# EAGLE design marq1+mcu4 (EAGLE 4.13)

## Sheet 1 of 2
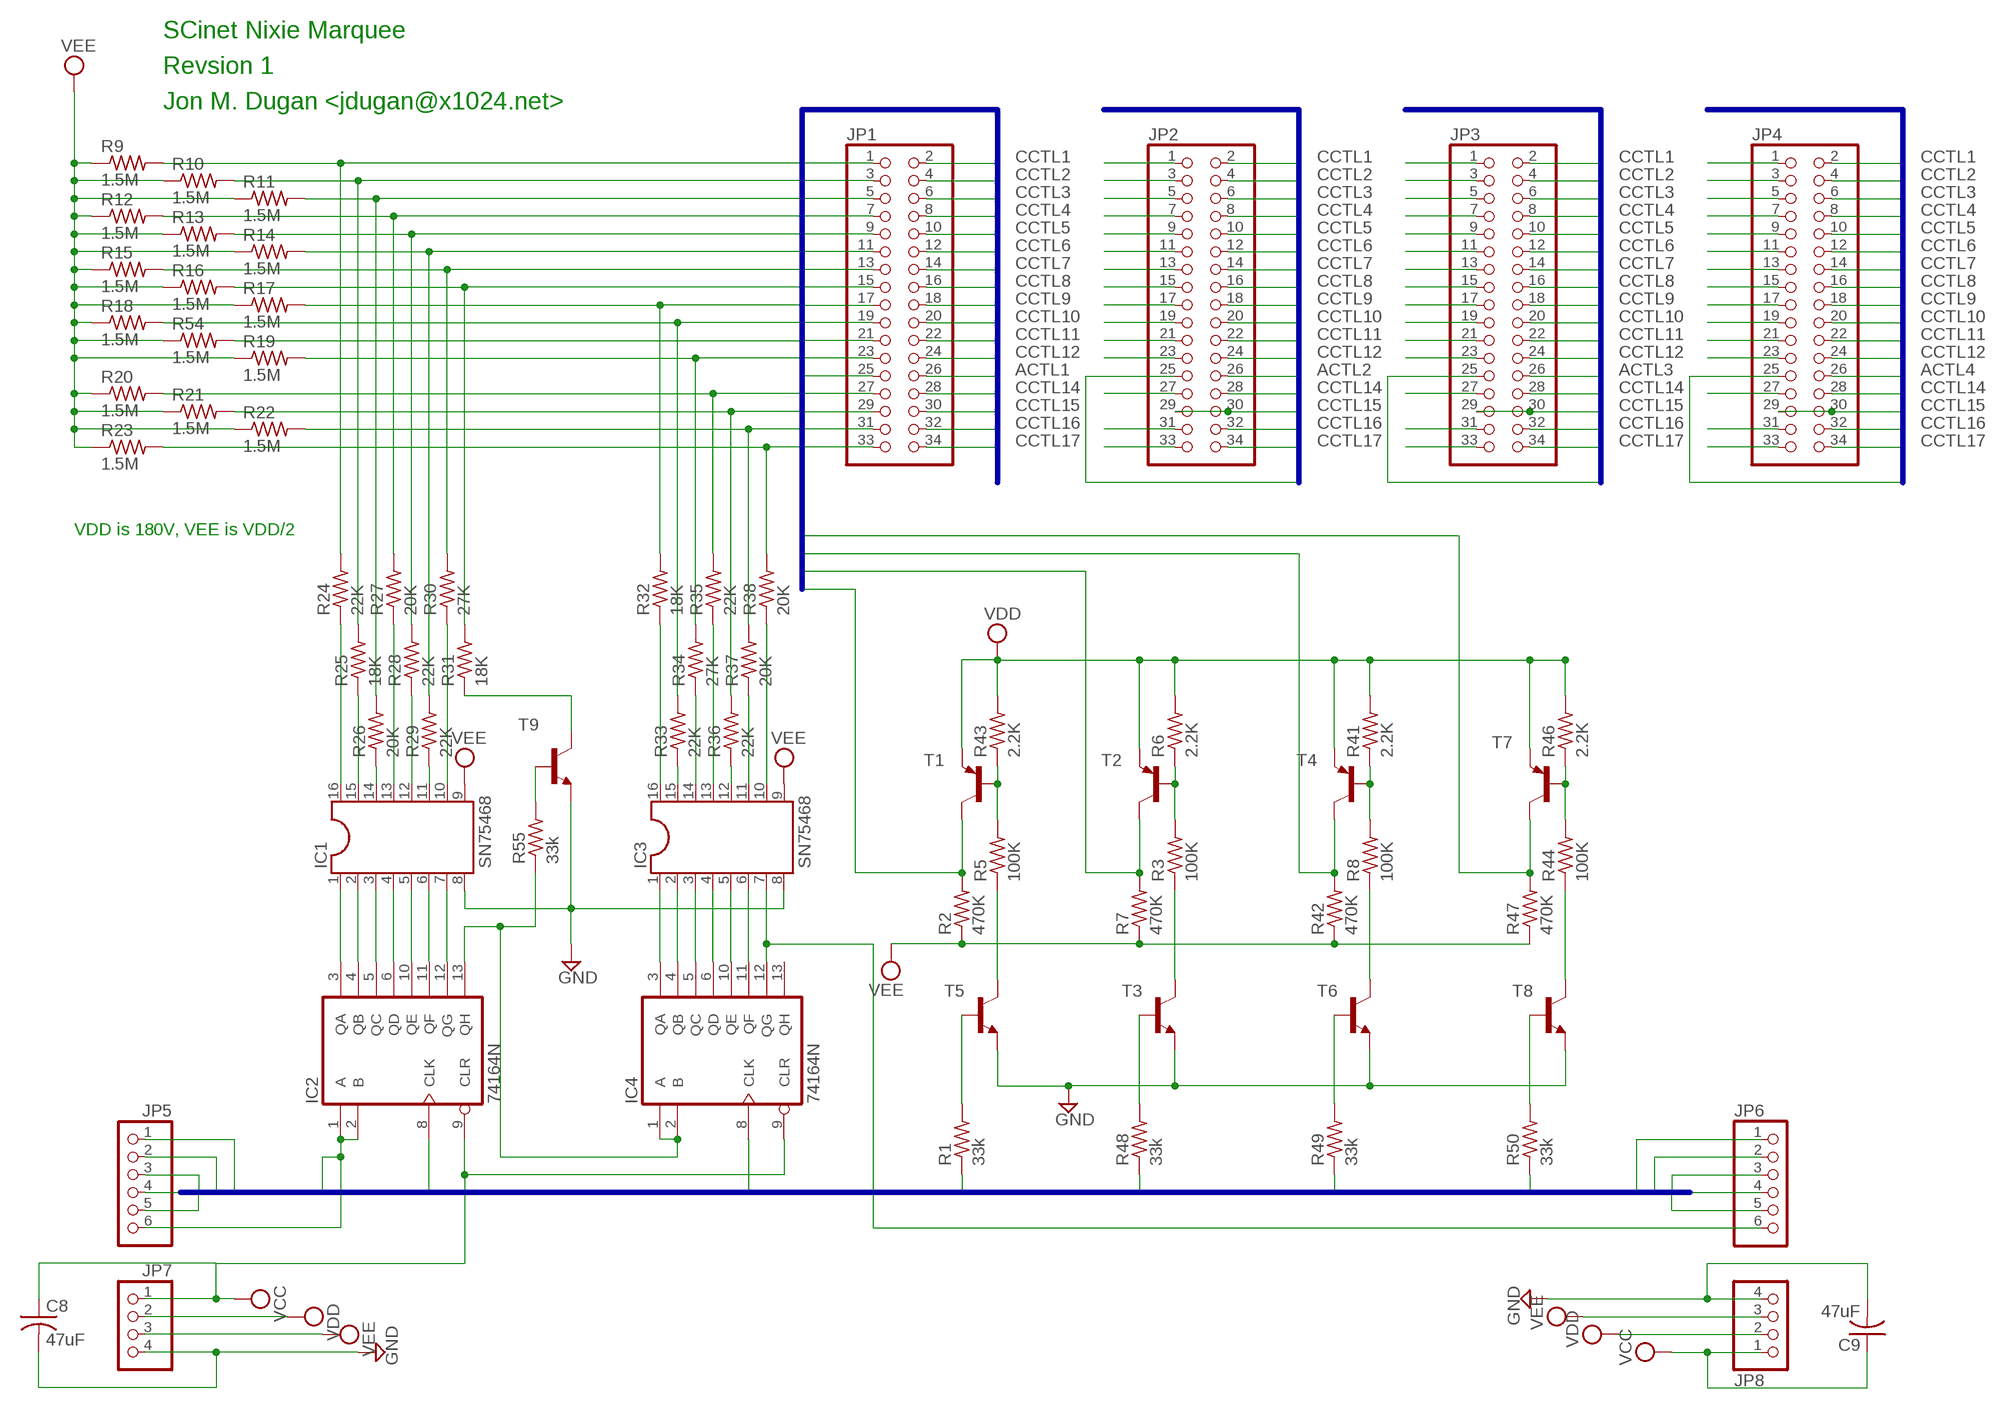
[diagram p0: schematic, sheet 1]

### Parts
C8  47uF  C-US025-050X050  [C025-050X050]
C9  47uF  C-US025-050X050  [C025-050X050]
IC1  SN75468  DIL16  [DIL16]
IC2  74164N  [DIL14]
IC3  SN75468  DIL16  [DIL16]
IC4  74164N  [DIL14]
JP1  PINHD-2X17  [2X17]
JP2  PINHD-2X17  [2X17]
JP3  PINHD-2X17  [2X17]
JP4  PINHD-2X17  [2X17]
JP5  PINHD-1X6  [1X06]
JP6  PINHD-1X6  [1X06]
JP7  PINHD-1X4  [1X04]
JP8  PINHD-1X4  [1X04]
R1  33k  R-US_0309/10  [0309/10]
R2  470K  R-US_0309/12  [0309/12]
R3  100K  R-US_0309/10  [0309/10]
R5  100K  R-US_0309/10  [0309/10]
R6  2.2K  R-US_0309/10  [0309/10]
R7  470K  R-US_0309/12  [0309/12]
R8  100K  R-US_0309/10  [0309/10]
R9  1.5M  R-US_0309/10  [0309/10]
R10  1.5M  R-US_0309/10  [0309/10]
R11  1.5M  R-US_0309/10  [0309/10]
R12  1.5M  R-US_0309/10  [0309/10]
R13  1.5M  R-US_0309/10  [0309/10]
R14  1.5M  R-US_0309/10  [0309/10]
R15  1.5M  R-US_0309/10  [0309/10]
R16  1.5M  R-US_0309/10  [0309/10]
R17  1.5M  R-US_0309/10  [0309/10]
R18  1.5M  R-US_0309/10  [0309/10]
R19  1.5M  R-US_0309/10  [0309/10]
R20  1.5M  R-US_0309/10  [0309/10]
R21  1.5M  R-US_0309/10  [0309/10]
R22  1.5M  R-US_0309/10  [0309/10]
R23  1.5M  R-US_0309/10  [0309/10]
R24  22K  R-US_0309/10  [0309/10]
R25  18K  R-US_0309/10  [0309/10]
R26  20K  R-US_0309/10  [0309/10]
R27  20K  R-US_0309/10  [0309/10]
R28  22K  R-US_0309/10  [0309/10]
R29  22K  R-US_0309/10  [0309/10]
R30  27K  R-US_0309/10  [0309/10]
R31  18K  R-US_0309/10  [0309/10]
R32  18K  R-US_0309/10  [0309/10]
R33  22K  R-US_0309/10  [0309/10]
R34  27K  R-US_0309/10  [0309/10]
R35  22K  R-US_0309/10  [0309/10]
R36  22K  R-US_0309/10  [0309/10]
R37  20K  R-US_0309/10  [0309/10]
R38  20K  R-US_0309/10  [0309/10]
R41  2.2K  R-US_0309/10  [0309/10]
R42  470K  R-US_0309/12  [0309/12]
R43  2.2K  R-US_0309/10  [0309/10]
R44  100K  R-US_0309/10  [0309/10]
R46  2.2K  R-US_0309/10  [0309/10]
R47  470K  R-US_0309/12  [0309/12]
R48  33k  R-US_0309/10  [0309/10]
R49  33k  R-US_0309/10  [0309/10]
R50  33k  R-US_0309/10  [0309/10]
R54  1.5M  R-US_0309/10  [0309/10]
R55  33k  R-US_0309/10  [0309/10]
T1  MPSW92-PNP-TO92-CBE  [TO92-CBE]
T2  MPSW92-PNP-TO92-CBE  [TO92-CBE]
T3  MPSA42-NPN-TO92-CBE  [TO92-CBE]
T4  MPSW92-PNP-TO92-CBE  [TO92-CBE]
T5  MPSA42-NPN-TO92-CBE  [TO92-CBE]
T6  MPSA42-NPN-TO92-CBE  [TO92-CBE]
T7  MPSW92-PNP-TO92-CBE  [TO92-CBE]
T8  MPSA42-NPN-TO92-CBE  [TO92-CBE]
T9  MPSA42-NPN-TO92-CBE  [TO92-CBE]

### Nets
A0: JP5.1 JP6.1 R1.1 ; also sheet 2
A1: JP5.2 JP6.2 R48.1 ; also sheet 2
A2: JP5.3 JP6.3 R49.1 ; also sheet 2
A3: JP5.4 JP6.4 R50.1 ; also sheet 2
ACTL1 [VEE]: JP1.25 JP1.26 R2.2 T1.C
ACTL2 [VEE]: JP2.25 JP2.26 R7.2 T2.C
ACTL3 [VEE]: JP3.25 JP3.26 R42.2 T4.C
ACTL4 [VEE]: JP4.25 JP4.26 R47.2 T7.C
CCTL1 [VEE]: JP1.1 JP1.2 JP2.1 JP2.2 JP3.1 JP3.2 JP4.1 JP4.2 R9.2 R24.2
CCTL2 [VEE]: JP1.3 JP1.4 JP2.3 JP2.4 JP3.3 JP3.4 JP4.3 JP4.4 R10.2 R25.2
CCTL3 [VEE]: JP1.5 JP1.6 JP2.5 JP2.6 JP3.5 JP3.6 JP4.5 JP4.6 R11.2 R26.2
CCTL4 [VEE]: JP1.7 JP1.8 JP2.7 JP2.8 JP3.7 JP3.8 JP4.7 JP4.8 R12.2 R27.2
CCTL5 [VEE]: JP1.9 JP1.10 JP2.9 JP2.10 JP3.9 JP3.10 JP4.9 JP4.10 R13.2 R28.2
CCTL6 [VEE]: JP1.11 JP1.12 JP2.11 JP2.12 JP3.11 JP3.12 JP4.11 JP4.12 R14.2 R29.2
CCTL7 [VEE]: JP1.13 JP1.14 JP2.13 JP2.14 JP3.13 JP3.14 JP4.13 JP4.14 R15.2 R30.2
CCTL8 [VEE]: JP1.15 JP1.16 JP2.15 JP2.16 JP3.15 JP3.16 JP4.15 JP4.16 R16.2 R31.2
CCTL9 [VEE]: JP1.17 JP1.18 JP2.17 JP2.18 JP3.17 JP3.18 JP4.17 JP4.18 R17.2 R32.2
CCTL10 [VEE]: JP1.19 JP1.20 JP2.19 JP2.20 JP3.19 JP3.20 JP4.19 JP4.20 R18.2 R33.2
CCTL11 [VEE]: JP1.21 JP1.22 JP2.21 JP2.22 JP3.21 JP3.22 JP4.21 JP4.22 R54.2
CCTL12 [VEE]: JP1.23 JP1.24 JP2.23 JP2.24 JP3.23 JP3.24 JP4.23 JP4.24 R19.2 R34.2
CCTL14 [VEE]: JP1.27 JP1.28 JP2.27 JP2.28 JP3.27 JP3.28 JP4.27 JP4.28 R20.2 R35.2
CCTL15 [VEE]: JP1.29 JP1.30 JP2.29 JP2.30 JP3.29 JP3.30 JP4.29 JP4.30 R21.2 R36.2
CCTL16 [VEE]: JP1.31 JP1.32 JP2.31 JP2.32 JP3.31 JP3.32 JP4.31 JP4.32 R22.2 R37.2
CCTL17 [VEE]: JP1.33 JP1.34 JP2.33 JP2.34 JP3.33 JP3.34 JP4.33 JP4.34 R23.2 R38.2
CLK: IC2.8(CLK) IC4.8(CLK) JP5.5 JP6.5 ; also sheet 2
D: IC2.1(A) IC2.2(B) JP5.6 ; also sheet 2
GND: C8.2 C9.2 IC1.8 IC3.8 JP7.4 JP8.4 T3.E T5.E T6.E T8.E T9.E ; also sheet 2
N$1: IC1.1 IC2.3(QA)
N$2: IC1.2 IC2.4(QB)
N$3: IC1.3 IC2.5(QC)
N$4: IC1.4 IC2.6(QD)
N$5: IC1.5 IC2.10(QE)
N$6: IC1.6 IC2.11(QF)
N$7 [VEE]: IC3.16 R32.1
N$8: IC3.1 IC4.3(QA)
N$9: IC3.2 IC4.4(QB)
N$10: IC3.3 IC4.5(QC)
N$11: IC3.4 IC4.6(QD)
N$12: IC3.5 IC4.10(QE)
N$13: IC3.6 IC4.11(QF)
N$26: R1.2 T5.B
N$27 [VEE]: R31.1 T9.C
N$29: IC3.7 IC4.12(QG) JP6.6
N$33 [VEE]: R5.1 T5.C
N$34 [VEE]: R5.2 R43.1 T1.B
N$37: R48.2 T3.B
N$38 [VEE]: R3.1 T3.C
N$39 [VEE]: R3.2 R6.1 T2.B
N$42: R49.2 T6.B
N$43 [VEE]: R8.1 T6.C
N$44 [VEE]: R8.2 R41.1 T4.B
N$45: R50.2 T8.B
N$46: R55.2 T9.B
N$47 [VEE]: IC1.16 R24.1
N$48: IC1.7 IC2.12(QG)
N$50: IC2.13(QH) IC4.1(A) IC4.2(B) R55.1
N$51 [VEE]: IC3.15 R33.1
N$52 [VEE]: IC3.14 R34.1
N$53 [VEE]: IC3.13 R35.1
N$54 [VEE]: IC3.12 R36.1
N$55 [VEE]: IC3.11 R37.1
N$56 [VEE]: IC3.10 R38.1
N$57 [VEE]: IC1.15 R25.1
N$59 [VEE]: R44.1 T8.C
N$60 [VEE]: R44.2 R46.1 T7.B
N$63 [VEE]: IC1.14 R26.1
N$64 [VEE]: IC1.13 R27.1
N$65 [VEE]: IC1.12 R28.1
N$66 [VEE]: IC1.11 R29.1
N$67 [VEE]: IC1.10 R30.1
VCC: C8.1 C9.1 IC2.9(CLR) IC4.9(CLR) JP7.1 JP8.1 ; also sheet 2
VDD [VEE]: JP7.2 JP8.2 R6.2 R41.2 R43.2 R46.2 T1.E T2.E T4.E T7.E ; also sheet 2
VEE [VEE]: IC1.9 IC3.9 JP7.3 JP8.3 R2.1 R7.1 R9.1 R10.1 R11.1 R12.1 R13.1 R14.1 R15.1 R16.1 R17.1 R18.1 R19.1 R20.1 R21.1 R22.1 R23.1 R42.1 R47.1 R54.1 ; also sheet 2
Unconnected: IC4.13(QH)

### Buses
BUS:A[0..3],CLK,D
BUS2:ACTL[1..4],CCTL[1..17]

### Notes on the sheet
- SCinet Nixie Marquee
- Revsion 1
- Jon M. Dugan <jdugan@x1024.net>
- VDD is 180V, VEE is VDD/2

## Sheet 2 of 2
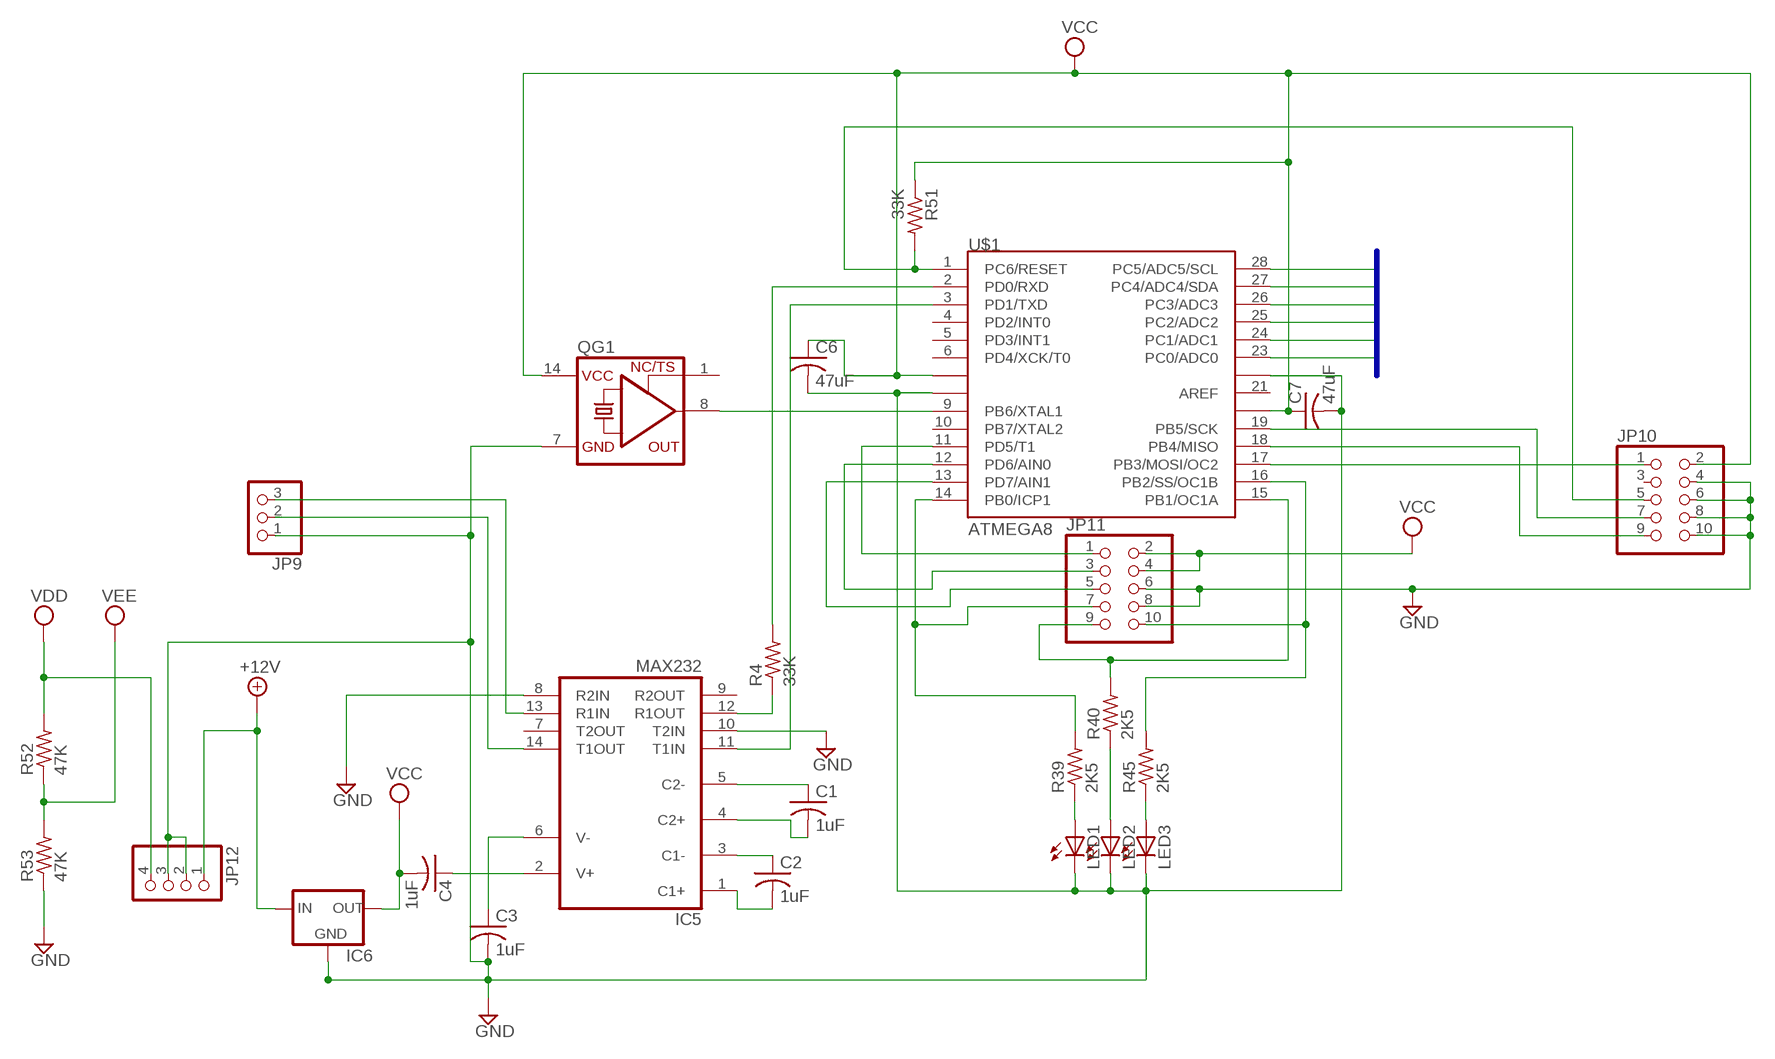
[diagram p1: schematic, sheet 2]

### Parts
C1  1uF  C-US025-060X050  [C025-060X050]
C2  1uF  C-US025-060X050  [C025-060X050]
C3  1uF  C-US025-060X050  [C025-060X050]
C4  1uF  C-US025-060X050  [C025-060X050]
C6  47uF  C-US025-050X050  [C025-050X050]
C7  47uF  C-US025-050X050  [C025-050X050]
IC5  MAX232  [DIL16]
IC6  78XXS  [78XXS]
JP9  PINHD-1X3  [1X03]
JP10  PINHD-2X5  [2X05]
JP11  PINHD-2X5  [2X05]
JP12  PINHD-1X4  [1X04]
LED1  LED3MM  [LED3MM]
LED2  LED3MM  [LED3MM]
LED3  LED3MM  [LED3MM]
QG1  XO-14  [DIL14S]
R4  33K  R-US_0309/10  [0309/10]
R39  2K5  R-US_0309/10  [0309/10]
R40  2K5  R-US_0309/10  [0309/10]
R45  2K5  R-US_0309/10  [0309/10]
R51  33K  R-US_0309/10  [0309/10]
R52  47K  R-US_0309/10  [0309/10]
R53  47K  R-US_0309/10  [0309/10]
U$1  ATMEGA8  [DIL28-3]

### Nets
+12V: IC6.IN JP12.1
A0: U$1.23(PC0/ADC0) ; also sheet 1
A1: U$1.24(PC1/ADC1) ; also sheet 1
A2: U$1.25(PC2/ADC2) ; also sheet 1
A3: U$1.26(PC3/ADC3) ; also sheet 1
CLK: U$1.27(PC4/ADC4/SDA) ; also sheet 1
D: U$1.28(PC5/ADC5/SCL) ; also sheet 1
GND: C3.2 C6.2 C7.2 IC5.8(R2IN) IC5.10(T2IN) IC6.GND JP9.1 JP10.4 JP10.6 JP10.8 JP10.10 JP11.6 JP11.8 JP12.2 JP12.3 LED1.K(C) LED2.K(C) LED3.K(C) QG1.7(GND) R53.1 U$1.8(GND) U$1.22(GN) ; also sheet 1
N$14: IC5.14(T1OUT) JP9.2
N$15: IC5.13(R1IN) JP9.3
N$16: JP11.1 U$1.11(PD5/T1)
N$17: JP11.3 U$1.12(PD6/AIN0)
N$18: JP11.5 U$1.13(PD7/AIN1)
N$19: JP10.1 U$1.17(PB3/MOSI/OC2)
N$20: JP10.5 R51.2 U$1.1(PC6/RESET)
N$21: JP10.9 U$1.18(PB4/MISO)
N$22: JP10.7 U$1.19(PB5/SCK)
N$23: LED1.A R39.1
N$24: LED2.A R40.1
N$25: LED3.A R45.1
N$28: R4.2 U$1.2(PD0/RXD)
N$30: IC5.11(T1IN) U$1.3(PD1/TXD)
N$31: C1.1 IC5.5(C2-)
N$32: C1.2 IC5.4(C2+)
N$35: C2.2 IC5.1(C1+)
N$36: QG1.8(OUT) U$1.9(PB6/XTAL1)
N$40: C2.1 IC5.3(C1-)
N$41: C4.1 IC5.2(V+)
N$49: IC5.12(R1OUT) R4.1
N$61: C3.1 IC5.6(V-)
N$68: JP11.7 R39.2 U$1.14(PB0/ICP1)
N$69: JP11.9 R40.2 U$1.15(PB1/OC1A)
N$70: JP11.10 R45.2 U$1.16(PB2/SS/OC1B)
VCC: C4.2 C6.1 C7.1 IC6.OUT JP10.2 JP11.2 JP11.4 QG1.14(VCC) R51.1 U$1.7(PWR) U$1.20(AVCC) ; also sheet 1
VDD [VEE]: JP12.4 R52.2 ; also sheet 1
VEE [VEE]: R52.1 R53.2 ; also sheet 1
Unconnected: IC5.7(T2OUT) IC5.9(R2OUT) JP10.3 QG1.1(TS) U$1.4(PD2/INT0) U$1.5(PD3/INT1) U$1.6(PD4/XCK/T0) U$1.10(PB7/XTAL2) U$1.21(AREF)

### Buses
BUS:A[0..3],CLK,D

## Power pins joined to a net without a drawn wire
GND: IC2.7(GND) IC4.7(GND) IC5.15(GND)
VCC: IC2.14(VCC) IC4.14(VCC) IC5.16(VCC)

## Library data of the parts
C1-C4 C6-C9 = rcl:C-US: CAPACITOR, American symbol
IC1 IC3 = ic-package:DIL16: Dual In Line
IC2 IC4 = 74xx-us:74*164: 8-bit parallel out SHIFT REGISTER
IC5 = maxim:MAX232: RS232 TRANSEIVER
IC6 = v-reg:78XXS: VOLTAGE REGULATOR
JP1-JP4 = pinhead:PINHD-2X17: PIN HEADER
JP5 JP6 = pinhead:PINHD-1X6: PIN HEADER
JP7 JP8 JP12 = pinhead:PINHD-1X4: PIN HEADER
JP9 = pinhead:PINHD-1X3: PIN HEADER
JP10 JP11 = pinhead:PINHD-2X5: PIN HEADER
LED1-LED3 = led:LED: LED
QG1 = crystal:XO-: CRYSTAL
R1-R55 = rcl:R-US_: RESISTOR, American symbol
T1 T2 T4 T7 = transistor:*-PNP-: PNP Transistror
T3 T5 T6 T8 T9 = transistor:*-NPN-: NPN Transistror
U$1 = mega8:ATMEGA8

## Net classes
0 default: width 0.254 mm
1 VEE: width 0.254 mm, drill 1.27 mm

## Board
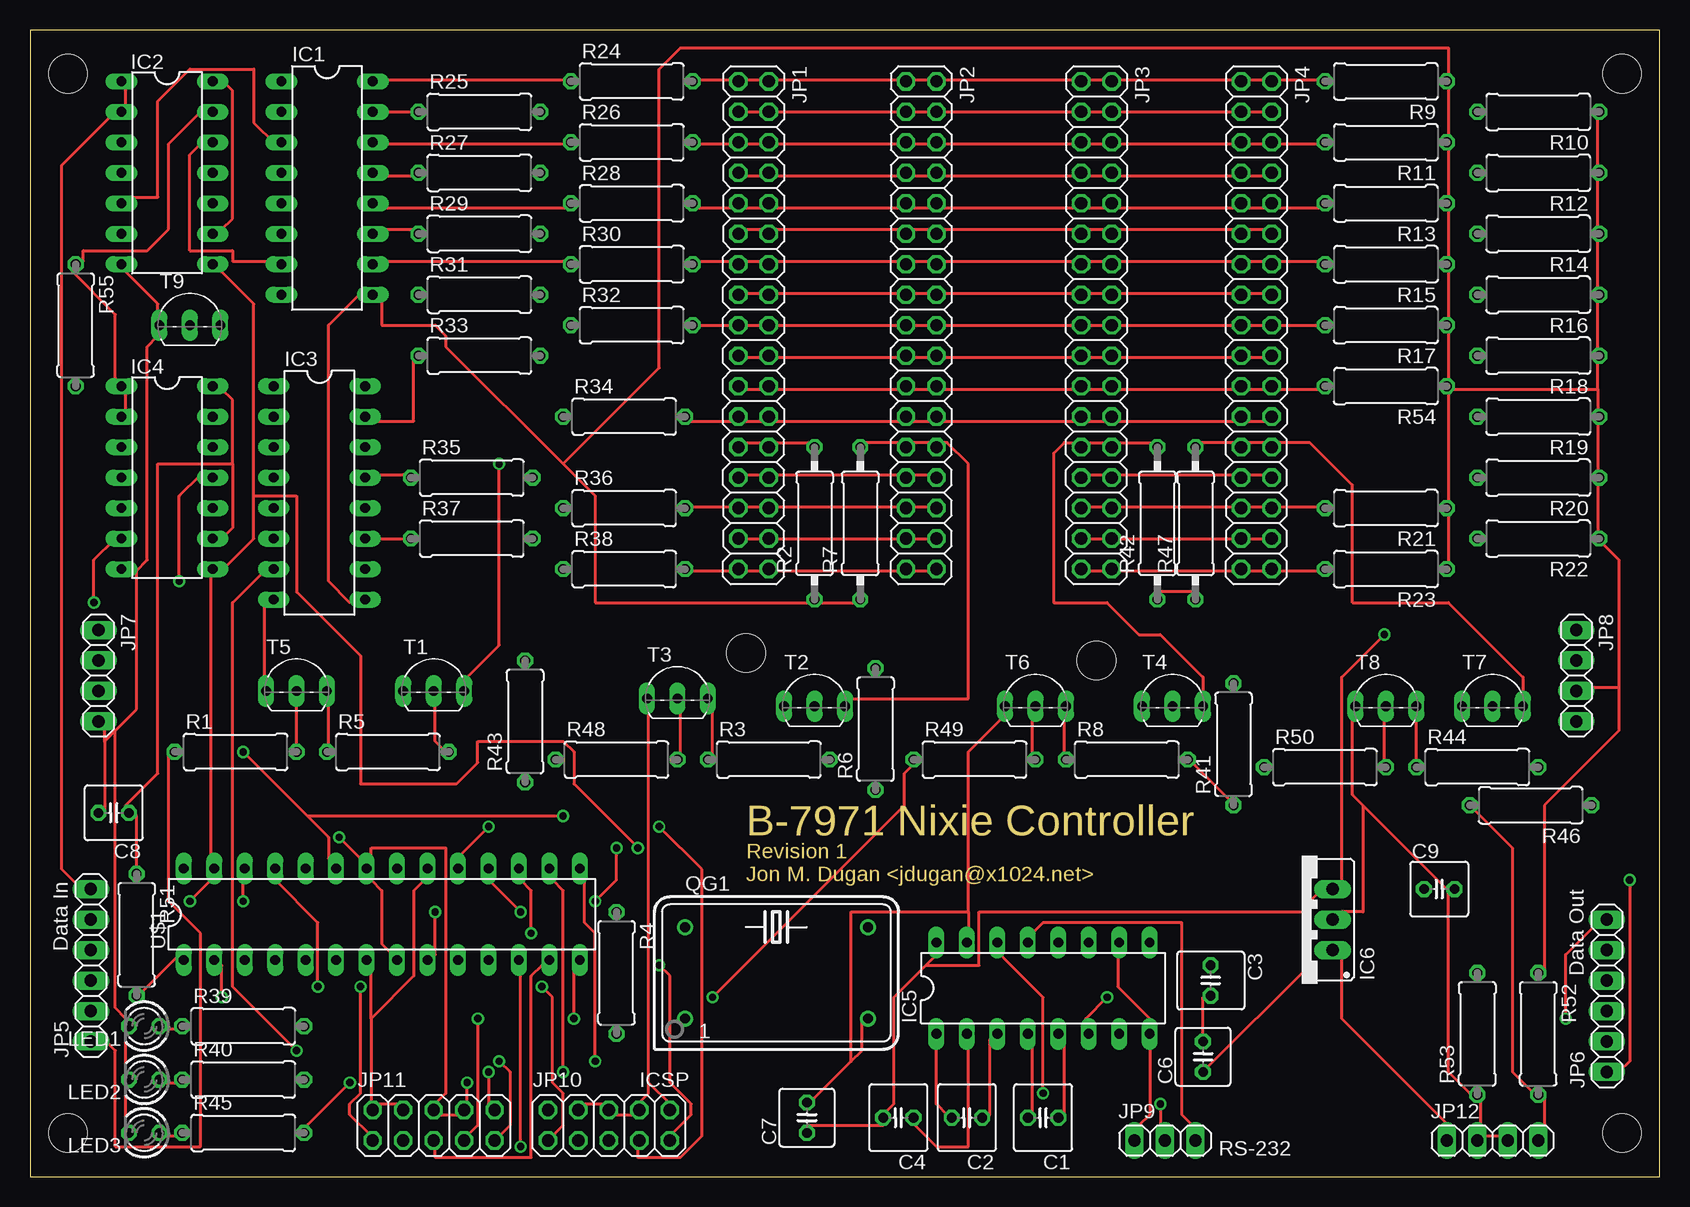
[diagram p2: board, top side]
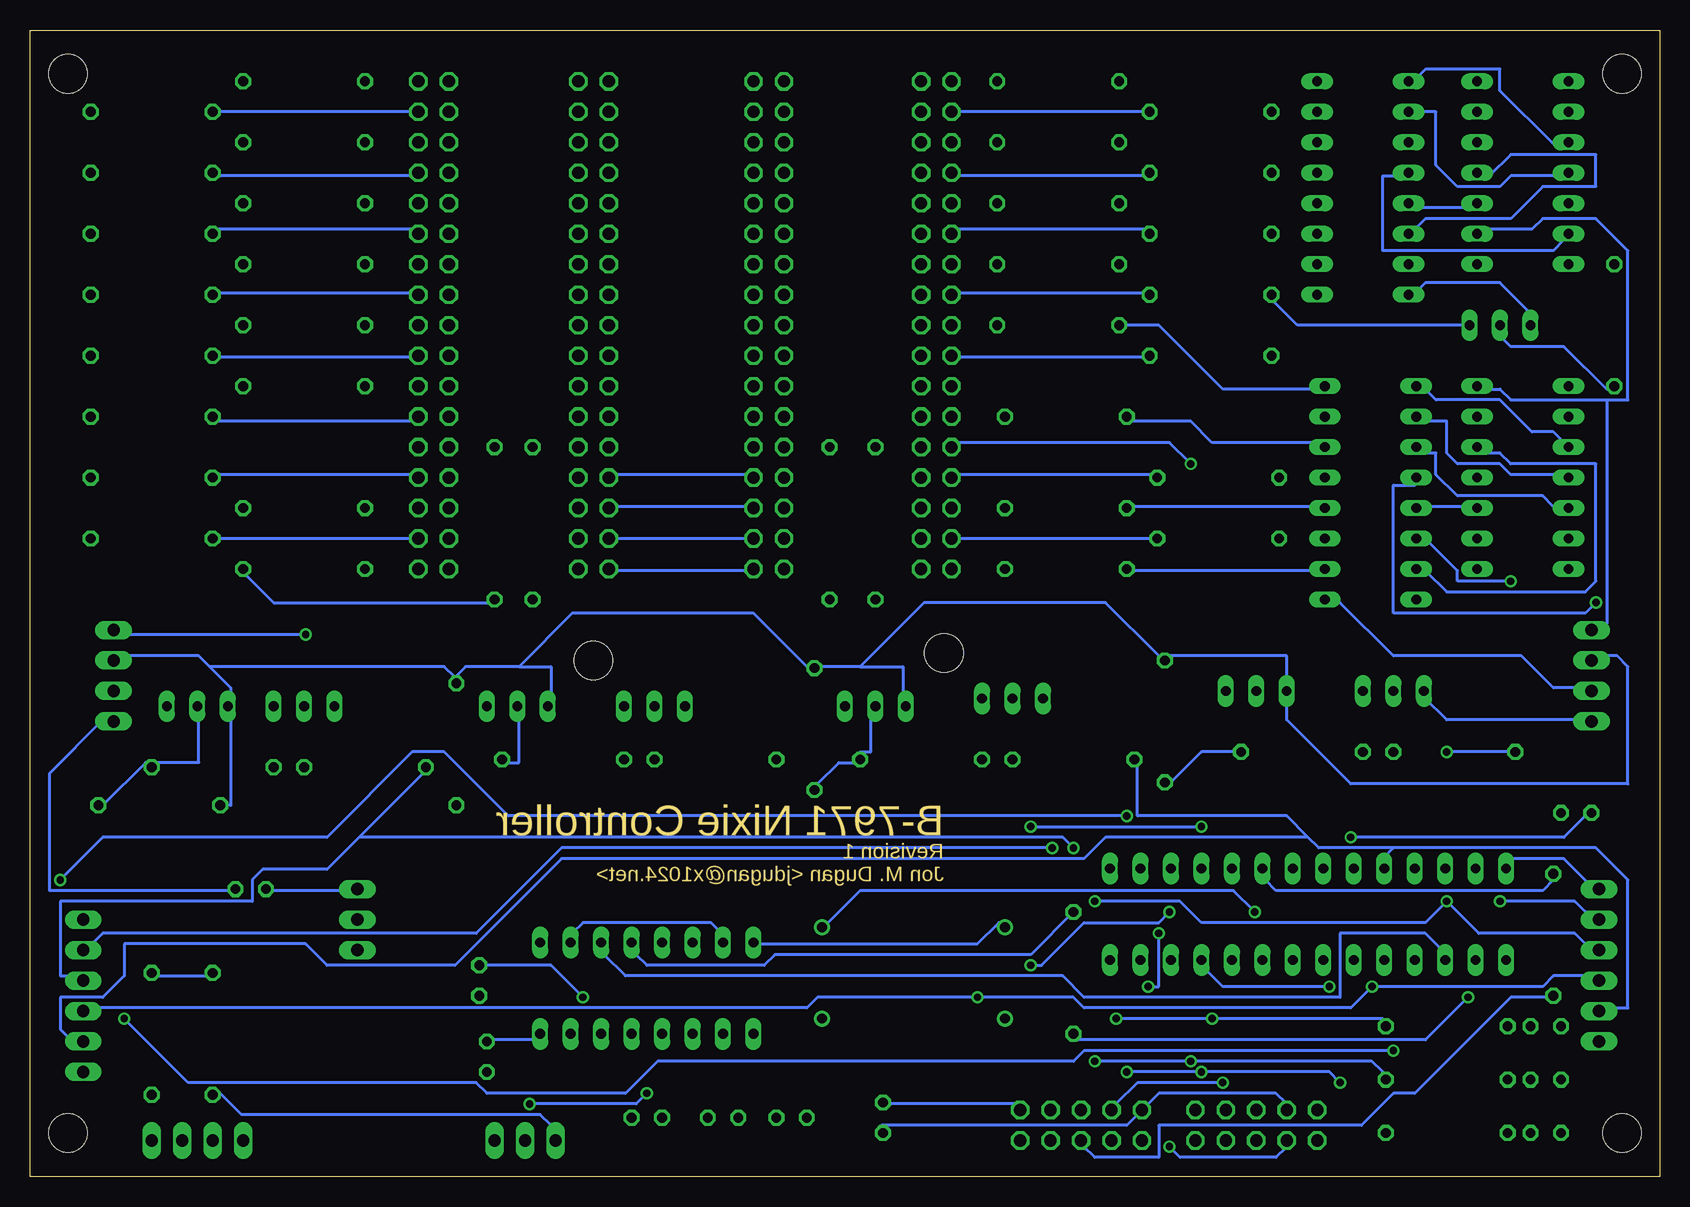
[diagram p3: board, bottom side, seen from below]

Size 135.87 x 95.55 mm. Coordinates in mm from the lower left corner, seen from the top.
Outline: 0,0 135.87,0 135.87,95.55 0,95.55 0,0
Copper layers (1*16): Top 0.035mm / dielectric 1.5mm / Bottom 0.035mm
Design rules "default": minimum track width 8mil, minimum drill 24mil, track to track 8mil, track to pad 8mil, pad to pad 8mil, via to via 8mil, smd to smd 8mil, copper to edge 40mil, drill to drill 8mil, minimum pad ring 10mil, minimum via ring 8mil, stop-mask expansion 4mil, vias tented up to drill 0mil, thermal gap 10mil
Holes 3.2 mm at 3.17,91.91 132.71,91.91 132.71,3.65 3.17,3.65 59.68,43.65 88.9,43.02

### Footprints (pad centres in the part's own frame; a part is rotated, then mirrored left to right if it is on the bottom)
C025-060X050 = drill 0.813 octagon: 1 -1.27,0; 2 1.27,0
C025-050X050 = drill 0.813 octagon: 1 -1.27,0; 2 1.27,0
DIL16 = drill 0.813 long: 1 -8.89,-3.81; 2 -6.35,-3.81; 3 -3.81,-3.81; 4 -1.27,-3.81; 5 1.27,-3.81; 6 3.81,-3.81; 7 6.35,-3.81; 8 8.89,-3.81; 9 8.89,3.81; 10 6.35,3.81; 11 3.81,3.81; 12 1.27,3.81; 13 -1.27,3.81; 14 -3.81,3.81; 15 -6.35,3.81; 16 -8.89,3.81
DIL14 = drill 0.813 long: 1 -7.62,-3.81; 2 -5.08,-3.81; 3 -2.54,-3.81; 4 0,-3.81; 5 2.54,-3.81; 6 5.08,-3.81; 7 7.62,-3.81; 8 7.62,3.81; 9 5.08,3.81; 10 2.54,3.81; 11 0,3.81; 12 -2.54,3.81; 13 -5.08,3.81; 14 -7.62,3.81
78XXS = drill 1.016 long: GND 0,-2.54; IN -2.54,-2.54; OUT 2.54,-2.54
2X17 = drill 1.016 octagon: 1 -20.32,-1.27; 2 -20.32,1.27; 3 -17.78,-1.27; 4 -17.78,1.27; 5 -15.24,-1.27; 6 -15.24,1.27; 7 -12.7,-1.27; 8 -12.7,1.27; 9 -10.16,-1.27; 10 -10.16,1.27; 11 -7.62,-1.27; 12 -7.62,1.27; 13 -5.08,-1.27; 14 -5.08,1.27; 15 -2.54,-1.27; 16 -2.54,1.27; 17 0,-1.27; 18 0,1.27; 19 2.54,-1.27; 20 2.54,1.27; 21 5.08,-1.27; 22 5.08,1.27; 23 7.62,-1.27; 24 7.62,1.27; 25 10.16,-1.27; 26 10.16,1.27; 27 12.7,-1.27; 28 12.7,1.27; 29 15.24,-1.27; 30 15.24,1.27; 31 17.78,-1.27; 32 17.78,1.27; 33 20.32,-1.27; 34 20.32,1.27
1X06 = drill 1.016 long: 1 -6.35,0; 2 -3.81,0; 3 -1.27,0; 4 1.27,0; 5 3.81,0; 6 6.35,0
1X04 = drill 1.016 long: 1 -3.81,0; 2 -1.27,0; 3 1.27,0; 4 3.81,0
1X03 = drill 1.016 long: 1 -2.54,0; 2 0,0; 3 2.54,0
2X05 = drill 1.016 octagon: 1 -5.08,-1.27; 2 -5.08,1.27; 3 -2.54,-1.27; 4 -2.54,1.27; 5 0,-1.27; 6 0,1.27; 7 2.54,-1.27; 8 2.54,1.27; 9 5.08,-1.27; 10 5.08,1.27
LED3MM = drill 0.813 octagon: A -1.27,0; K 1.27,0
DIL14S = drill 0.813 round: 1 -7.62,-3.81; 7 7.62,-3.81; 8 7.62,3.81; 14 -7.62,3.81
0309/10 = drill 0.813 octagon: 1 -5.08,0; 2 5.08,0
0309/12 = drill 0.813 octagon: 1 -6.35,0; 2 6.35,0
TO92-CBE = drill 0.813 long: B 0,0; C 2.54,0; E -2.54,0
DIL28-3 = drill 0.813 long: 1 -17.02,-4; 2 -14.48,-4; 3 -11.94,-4; 4 -9.4,-4; 5 -6.86,-4; 6 -4.32,-4; 7 -1.78,-4; 8 0.76,-4; 9 3.3,-4; 10 5.84,-4; 11 8.38,-4; 12 10.92,-4; 13 13.46,-4; 14 16,-4; 15 16,3.62; 16 13.46,3.62; 17 10.92,3.62; 18 8.38,3.62; 19 5.84,3.62; 20 3.3,3.62; 21 0.76,3.62; 22 -1.78,3.62; 23 -4.32,3.62; 24 -6.86,3.62; 25 -9.4,3.62; 26 -11.94,3.62; 27 -14.48,3.62; 28 -17.02,3.62

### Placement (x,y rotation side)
C1  84.45,4.92 180 top
C2  78.1,4.92 180 top
C3  98.42,16.35 270 top
C4  72.39,4.92 180 top
C6  97.79,10 90 top
C7  64.77,4.92 90 top
C8  6.98,30.32 180 top
C9  117.47,23.96 0 top
IC1  24.76,82.38 270 top
IC2  11.42,83.65 270 top
IC3  24.12,56.98 270 top
IC4  11.42,58.26 270 top
IC5  84.45,15.71 0 top
IC6  106.04,21.43 90 top
JP1  60.32,70.95 270 top
JP2  74.29,70.95 270 top
JP3  88.9,70.95 270 top
JP4  102.23,70.95 270 top
JP5  5.08,17.62 90 top
JP6  131.44,15.08 90 top
JP7  5.71,41.74 270 top
JP8  128.9,41.74 270 top
JP9  94.61,3.01 0 top
JP10  48.25,4.28 0 top
JP11  33.65,4.28 0 top
JP12  121.92,3.01 0 top
LED1  9.52,12.54 180 top
LED2  9.52,8.09 180 top
LED3  9.52,3.65 180 top
QG1  62.22,16.98 0 top
R1  17.14,35.4 0 top
R2  65.4,54.45 90 top
R3  61.59,34.76 0 top
R4  48.89,16.98 270 top
R5  29.84,35.4 0 top
R6  70.48,37.3 90 top
R7  69.21,54.45 90 top
R8  91.44,34.76 0 top
R9  113.03,91.27 180 top
R10  125.73,88.73 180 top
R11  113.03,86.19 180 top
R12  125.73,83.65 180 top
R13  113.03,81.11 180 top
R14  125.73,78.57 180 top
R15  113.03,76.03 180 top
R16  125.73,73.49 180 top
R17  113.03,70.95 180 top
R18  125.73,68.41 180 top
R19  125.73,63.34 180 top
R20  125.73,58.26 180 top
R21  113.03,55.72 180 top
R22  125.73,53.18 180 top
R23  113.03,50.63 180 top
R24  50.16,91.27 0 top
R25  37.46,88.73 0 top
R26  50.16,86.19 0 top
R27  37.46,83.65 0 top
R28  50.16,81.11 0 top
R29  37.46,78.57 0 top
R30  50.16,76.03 0 top
R31  37.46,73.49 0 top
R32  50.16,70.95 0 top
R33  37.46,68.41 0 top
R34  49.52,63.34 0 top
R35  36.82,58.26 0 top
R36  49.52,55.72 0 top
R37  36.82,53.18 0 top
R38  49.52,50.63 0 top
R39  17.78,12.54 0 top
R40  17.78,8.09 0 top
R41  100.33,36.03 90 top
R42  93.98,54.45 90 top
R43  41.27,37.94 90 top
R44  120.65,34.12 0 top
R45  17.78,3.65 0 top
R46  125.09,30.95 180 top
R47  97.15,54.45 90 top
R48  48.89,34.76 0 top
R49  78.73,34.76 0 top
R50  107.95,34.12 0 top
R51  8.88,20.16 270 top
R52  125.73,11.9 270 top
R53  120.65,11.9 90 top
R54  113.03,65.88 180 top
R55  3.81,70.95 270 top
T1  33.65,40.48 0 top
T2  65.4,39.2 0 top
T3  53.97,39.84 0 top
T4  95.25,39.2 0 top
T5  22.22,40.48 0 top
T6  83.81,39.2 0 top
T7  121.92,39.2 0 top
T8  113.03,39.2 0 top
T9  13.33,70.95 0 top
U$1  29.84,22.06 0 top

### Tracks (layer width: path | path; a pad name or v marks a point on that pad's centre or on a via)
+12V
  Top 0.254: JP12.1 118.23,4.28 109.34,13.17 109.34,18.5 IC6.IN
A0  (via drill 0.61)
  Top 0.254: 23.11,30.06 24.89,28.28 24.89,26.51 U$1.23 | v17.78,35.4 23.11,30.06 | JP5.1 6.22,11.39 7.11,10.5 7.11,2.5 14.22,2.5 14.22,20.28 11.55,22.95 11.55,35.4 R1.1 | v133.34,24.73 133.34,9.61 132.46,8.73 JP6.1 | 23.11,30.06 v44.45,30.06
  Bottom 0.254: R1.1 v17.78,35.4 | v133.34,24.73 129.79,28.28 111.12,28.28 104.01,35.4 101.34,35.4 96.01,30.06 v44.45,30.06
A1
  Bottom 0.254: 22.22,27.39 23.11,26.51 U$1.24 | 22.22,27.39 5.33,27.39 2.66,24.73 2.66,14.06 4.44,14.06 JP5.2 | 29.33,28.28 28.44,27.39 22.22,27.39 | 29.33,28.28 31.11,30.06 43.56,30.06 43.56,34.51 R48.1 | 29.33,28.28 46.22,28.28 48,26.51 91.56,26.51 100.45,17.62 111.12,17.62 112.9,19.39 128.01,19.39 128.01,16.73 129.79,14.95 133.34,14.95 133.34,12.28 132.46,11.39 JP6.2
A2  (via drill 0.61)
  Top 0.254: v24,15.84 24,21.17 20.44,24.73 U$1.25 | v56.89,14.95 72.89,30.95 72.89,33.62 73.78,34.51 R49.1
  Bottom 0.254: JP5.3 6.22,16.73 8.88,16.73 9.77,15.84 v24,15.84 25.78,14.06 48,14.06 48.89,14.95 v56.89,14.95 70.23,14.95 71.12,14.06 130.68,14.06 JP6.3
A3  (via drill 0.61)
  Top 0.254: v17.78,22.95 17.78,24.73 U$1.26 | v47.11,22.95 48.89,24.73 v48.89,27.39
  Bottom 0.254: JP5.4 6.22,19.39 7.11,20.28 15.11,20.28 v17.78,22.95 19.55,21.17 38.22,21.17 40,22.95 v47.11,22.95 | 108.45,28.28 111.12,25.62 116.45,25.62 117.34,24.73 117.34,22.95 133.34,22.95 133.34,16.73 132.46,16.73 JP6.4 | 108.45,28.28 103.12,33.62 R50.1 | v48.89,27.39 49.78,28.28 108.45,28.28
ACTL1  (via drill 0.61)
  Top 0.254: R2.2 64.89,61.18 62.22,61.18 JP1.26 61.34,61.18 59.56,61.18 JP1.25 | v39.11,59.4 39.11,44.29 36.44,41.62 T1.C
  Bottom 0.254: v39.11,59.4 40.89,61.18 58.67,61.18 JP1.25
ACTL2
  Top 0.254: 72.89,61.18 69.34,61.18 R7.2 | 75.56,61.18 76.45,61.18 78.23,59.4 78.23,39.84 68.45,39.84 T2.C | 75.56,61.18 72.89,61.18 | 72.89,61.18 JP2.25 | 75.56,61.18 JP2.26
ACTL3
  Top 0.254: R42.2 94.23,61.18 90.67,61.18 JP3.26 89.78,61.18 88.01,61.18 JP3.25 87.12,61.18 86.23,61.18 85.34,60.29 85.34,47.84 89.78,47.84 92.45,45.17 94.23,45.17 97.79,41.62 T4.C
ACTL4
  Top 0.254: R47.2 96.9,61.18 100.45,61.18 JP4.25 101.34,61.18 103.12,61.18 JP4.26 104.01,61.18 106.68,61.18 110.23,57.62 110.23,47.84 118.23,47.84 124.45,41.62 T7.C
CCTL1
  Top 0.254: 72.89,91.4 75.56,91.4 | R24.2 55.11,91.4 58.67,91.4 JP1.1 59.56,91.4 61.34,91.4 JP1.2 62.22,91.4 72.89,91.4 | 72.89,91.4 JP2.1 | R9.2 107.56,91.4 104.01,91.4 JP4.2 103.12,91.4 101.34,91.4 JP4.1 100.45,91.4 90.67,91.4 JP3.2 89.78,91.4 88.01,91.4 JP3.1 87.12,91.4 75.56,91.4 | 75.56,91.4 JP2.2
CCTL2
  Top 0.254: JP1.3 JP1.4 72.89,88.73 JP2.3 JP2.4 JP3.3 JP3.4 JP4.3 JP4.4
  Bottom 0.254: R25.2 JP1.3 | JP4.4 R10.2
CCTL3
  Top 0.254: 72.89,86.07 75.56,86.07 | R26.2 55.11,86.07 58.67,86.07 JP1.5 59.56,86.07 61.34,86.07 JP1.6 62.22,86.07 72.89,86.07 | 72.89,86.07 JP2.5 | R11.2 107.56,86.07 104.01,86.07 JP4.6 103.12,86.07 101.34,86.07 JP4.5 100.45,86.07 90.67,86.07 JP3.6 89.78,86.07 88.01,86.07 JP3.5 87.12,86.07 75.56,86.07 | 75.56,86.07 JP2.6
CCTL4
  Top 0.254: 72.89,83.4 75.56,83.4 | JP1.7 59.56,83.4 61.34,83.4 JP1.8 62.22,83.4 72.89,83.4 | 72.89,83.4 JP2.7 | JP4.8 103.12,83.4 101.34,83.4 JP4.7 100.45,83.4 90.67,83.4 JP3.8 89.78,83.4 88.01,83.4 JP3.7 87.12,83.4 75.56,83.4 | 75.56,83.4 JP2.8
  Bottom 0.254: R27.2 42.67,83.4 58.67,83.4 JP1.7 | R12.2 120.01,83.4 104.01,83.4 JP4.8
CCTL5
  Top 0.254: 72.89,80.73 75.56,80.73 | R28.2 55.11,80.73 58.67,80.73 JP1.9 59.56,80.73 61.34,80.73 JP1.10 62.22,80.73 72.89,80.73 | 72.89,80.73 JP2.9 | R13.2 107.56,80.73 104.01,80.73 JP4.10 103.12,80.73 101.34,80.73 JP4.9 100.45,80.73 90.67,80.73 JP3.10 89.78,80.73 88.01,80.73 JP3.9 87.12,80.73 75.56,80.73 | 75.56,80.73 JP2.10
CCTL6
  Top 0.254: 72.89,78.96 75.56,78.96 | JP1.11 59.56,78.96 61.34,78.96 JP1.12 62.22,78.96 72.89,78.96 | 72.89,78.96 JP2.11 | JP4.12 103.12,78.96 101.34,78.96 JP4.11 100.45,78.96 90.67,78.96 JP3.12 89.78,78.96 88.01,78.96 JP3.11 87.12,78.96 75.56,78.96 | 75.56,78.96 JP2.12
  Bottom 0.254: R29.2 42.67,78.96 58.67,78.96 JP1.11 | R14.2 120.9,78.96 104.01,78.96 JP4.12
CCTL7
  Top 0.254: 72.89,76.29 75.56,76.29 | R30.2 55.11,76.29 58.67,76.29 JP1.13 59.56,76.29 61.34,76.29 JP1.14 62.22,76.29 72.89,76.29 | 72.89,76.29 JP2.13 | R15.2 107.56,76.29 104.01,76.29 JP4.14 103.12,76.29 101.34,76.29 JP4.13 100.45,76.29 90.67,76.29 JP3.14 89.78,76.29 88.01,76.29 JP3.13 87.12,76.29 75.56,76.29 | 75.56,76.29 JP2.14
CCTL8
  Top 0.254: 72.89,73.62 75.56,73.62 | JP1.15 59.56,73.62 61.34,73.62 JP1.16 62.22,73.62 72.89,73.62 | 72.89,73.62 JP2.15 | JP4.16 103.12,73.62 101.34,73.62 JP4.15 100.45,73.62 90.67,73.62 JP3.16 89.78,73.62 88.01,73.62 JP3.15 87.12,73.62 75.56,73.62 | 75.56,73.62 JP2.16
  Bottom 0.254: R31.2 42.67,73.62 58.67,73.62 JP1.15 | R16.2 120.01,73.62 104.01,73.62 JP4.16
CCTL9
  Top 0.254: 55.11,70.95 R32.2 JP1.17 JP1.18 72.89,70.95 JP2.17 JP2.18 JP3.17 JP3.18 JP4.17 JP4.18 R17.2
CCTL10
  Top 0.254: 72.89,68.29 75.56,68.29 | JP1.19 59.56,68.29 61.34,68.29 JP1.20 62.22,68.29 72.89,68.29 | 72.89,68.29 JP2.19 | JP4.20 103.12,68.29 101.34,68.29 JP4.19 100.45,68.29 90.67,68.29 JP3.20 89.78,68.29 88.01,68.29 JP3.19 87.12,68.29 75.56,68.29 | 75.56,68.29 JP2.20
  Bottom 0.254: R33.2 42.67,68.29 58.67,68.29 JP1.19 | R18.2 120.01,68.29 104.01,68.29 JP4.20
CCTL11
  Top 0.254: JP1.21 59.56,65.62 61.34,65.62 JP1.22 62.22,65.62 72.89,65.62 | 72.89,65.62 75.56,65.62 | 72.89,65.62 JP2.21 | R54.2 107.56,65.62 104.01,65.62 JP4.22 103.12,65.62 101.34,65.62 JP4.21 100.45,65.62 90.67,65.62 JP3.22 89.78,65.62 88.01,65.62 JP3.21 87.12,65.62 75.56,65.62 | 75.56,65.62 JP2.22
CCTL12
  Top 0.254: 72.89,62.95 75.56,62.95 | R34.2 55.11,62.95 58.67,62.95 JP1.23 59.56,62.95 61.34,62.95 JP1.24 62.22,62.95 72.89,62.95 | 72.89,62.95 JP2.23 | JP4.24 103.12,62.95 101.34,62.95 JP4.23 100.45,62.95 90.67,62.95 JP3.24 89.78,62.95 88.01,62.95 JP3.23 87.12,62.95 75.56,62.95 | 75.56,62.95 JP2.24
  Bottom 0.254: R19.2 120.9,62.95 104.01,62.95 JP4.24
CCTL14
  Top 0.254: JP3.27 88.01,58.51 89.78,58.51 JP3.28 90.67,58.51 100.45,58.51 JP4.27 101.34,58.51 103.12,58.51 JP4.28 | 72.89,58.51 75.56,58.51 JP2.28 | JP1.27 59.56,58.51 61.34,58.51 JP1.28 62.22,58.51 72.89,58.51 | 72.89,58.51 JP2.27
  Bottom 0.254: R20.2 120.01,58.51 104.01,58.51 JP4.28 | R35.2 41.78,58.51 58.67,58.51 JP1.27 | JP3.27 87.12,58.51 75.56,58.51 JP2.28
CCTL15
  Top 0.254: JP3.29 88.01,55.84 89.78,55.84 JP3.30 90.67,55.84 100.45,55.84 JP4.29 101.34,55.84 103.12,55.84 JP4.30 104.01,55.84 107.56,55.84 R21.2 | 72.89,55.84 75.56,55.84 JP2.30 | R36.2 55.11,55.84 58.67,55.84 JP1.29 59.56,55.84 61.34,55.84 JP1.30 62.22,55.84 72.89,55.84 | 72.89,55.84 JP2.29
  Bottom 0.254: JP3.29 87.12,55.84 75.56,55.84 JP2.30
CCTL16
  Top 0.254: JP3.31 JP3.32 JP4.31 JP4.32 | JP2.32 JP2.31 72.89,53.18 JP1.32 JP1.31
  Bottom 0.254: JP4.32 R22.2 | 41.78,53.18 R37.2 JP1.31 | JP2.32 JP3.31
CCTL17
  Top 0.254: JP3.33 88.01,50.51 89.78,50.51 JP3.34 90.67,50.51 100.45,50.51 JP4.33 101.34,50.51 103.12,50.51 JP4.34 104.01,50.51 107.56,50.51 R23.2 | 72.89,50.51 75.56,50.51 JP2.34 | R38.2 55.11,50.51 58.67,50.51 JP1.33 59.56,50.51 61.34,50.51 JP1.34 62.22,50.51 72.89,50.51 | 72.89,50.51 JP2.33
  Bottom 0.254: JP3.33 87.12,50.51 75.56,50.51 JP2.34
CLK  (via drill 0.61)
  Top 0.254: 18.66,56.73 18.66,53.18 16,50.51 IC4.8 15.11,50.51 15.11,26.51 U$1.27 15.11,24.73 v13.33,22.95 | 18.66,56.73 18.66,72.73 16,75.4 IC2.8 | v50.67,27.39 45.33,32.73 45.33,35.4 44.45,36.28 37.33,36.28 37.33,34.51 35.55,32.73 27.55,32.73 27.55,43.4 22.22,48.73 22.22,56.73 18.66,56.73
  Bottom 0.254: v13.33,22.95 7.11,22.95 6.22,22.06 JP5.5 | v50.67,27.39 91.56,27.39 98.67,20.28 129.79,20.28 130.68,19.39 JP6.5
D
  Top 0.254: IC2.1 8,91.4 8,88.73 IC2.2 7.11,88.73 2.66,84.29 2.66,25.62 4.44,23.84 JP5.6
  Bottom 0.254: U$1.28 12.44,26.51 8,26.51 5.33,23.84 JP5.6
GND  (via drill 0.61)
  Top 0.254: IC2.7 8,75.4 10.66,72.73 10.66,71.84 T9.E 10.66,70.07 9.77,69.18 9.77,51.4 8.88,50.51 | LED3.K 8,4.28 8,7.84 LED2.K 8,8.73 8,12.28 LED1.K 8,13.17 7.11,14.06 7.11,37.17 | T5.E 19.55,41.62 19.55,47.84 IC3.8 | 6.22,36.28 6.22,38.06 JP7.4 | 6.22,36.28 6.22,30.06 C8.2 | 8.88,50.51 8.88,38.95 7.11,37.17 | 7.11,37.17 6.22,36.28 | 8.88,50.51 IC4.7 | JP12.3 122.68,3.39 120.9,3.39 JP12.2 120.9,4.28 120.9,6.95 R53.1 120.01,6.95 118.23,8.73 118.23,23.84 | 111.12,30.95 110.23,31.84 110.23,38.06 T8.E | 118.23,23.84 111.12,30.95 | 111.12,30.95 111.12,22.06 109.34,22.06 IC6.GND | 118.23,23.84 C9.2 | C6.2 97.79,14.95 C3.2 | JP9.1 92.45,4.28 93.34,5.17 IC5.8 93.34,13.17 90.67,15.84 90.67,18.5 IC5.10 | 78.23,22.06 78.23,20.28 IC5.15 | 78.23,22.06 78.23,35.4 80.89,38.06 T6.E | U$1.8 30.22,18.5 29.33,19.39 29.33,23.84 28.44,24.73 U$1.22 | U$1.22 28.44,26.51 28.44,27.39 34.67,27.39 34.67,6.95 33.78,6.06 JP11.6 33.78,5.17 35.55,5.17 JP11.8 36.44,6.06 v36.44,7.84 | 68.45,9.61 69.34,10.5 69.34,13.17 QG1.7 | 68.45,9.61 64.89,6.06 C7.2 | JP10.4 46.22,6.06 48,6.06 JP10.6 48.89,5.17 50.67,5.17 JP10.8 50.67,6.06 51.56,6.95 51.56,7.84 | 51.56,7.84 51.56,38.95 T3.E | 51.56,7.84 53.34,6.06 JP10.10 | 78.23,22.06 68.45,22.06 68.45,9.61 | v25.78,28.28 27.55,26.51 U$1.22
  Bottom 0.254: IC1.8 20.44,73.62 19.55,74.51 13.33,74.51 10.66,71.84 T9.E | T5.E 19.55,39.84 17.78,38.06 7.11,38.06 JP7.4 | JP8.4 129.79,38.06 134.23,33.62 134.23,23.84 119.12,23.84 C9.2 | IC5.8 93.34,11.39 97.79,11.39 C6.2 | IC5.15 78.23,20.28 79.12,21.17 89.78,21.17 90.67,20.28 IC5.10 | C7.2 64.89,6.06 53.34,6.06 JP10.10 | v36.44,7.84 43.56,7.84 45.33,6.06 JP10.4 | R53.1 120.01,6.95 118.23,5.17 93.34,5.17 92.45,4.28 JP9.1 | v25.78,28.28 8,28.28 6.22,30.06 C8.2
N$1
  Bottom 0.254: IC2.3 8.88,86.07 13.33,90.51 13.33,92.29 19.55,92.29 20.44,91.4 IC1.1
N$2
  Bottom 0.254: IC2.4 8.88,83.4 12.44,83.4 13.33,82.51 16.89,82.51 18.66,84.29 18.66,88.73 IC1.2
N$3
  Top 0.254: IC2.5 8,81.62 10.66,81.62 10.66,89.62 13.33,92.29 18.66,92.29 18.66,87.85 20.44,86.07 IC1.3
N$4
  Bottom 0.254: IC2.6 8,78.07 8.88,77.18 23.11,77.18 23.11,83.4 22.22,83.4 IC1.4
N$5
  Bottom 0.254: IC2.10 16,80.73 20.44,80.73 IC1.5
N$6
  Bottom 0.254: IC1.6 20.44,78.96 19.55,79.84 12.44,79.84 9.77,82.51 5.33,82.51 5.33,85.18 12.44,85.18 14.22,83.4 IC2.11
N$7
  Bottom 0.254: IC3.16 28.44,65.62 36.44,65.62 41.78,70.95 R32.1
N$8
  Bottom 0.254: IC4.3 8.88,62.06 10.66,62.06 13.33,64.73 18.66,64.73 19.55,65.62 IC3.1
N$9
  Bottom 0.254: IC4.4 8.88,58.51 12.44,58.51 13.33,59.4 16.89,59.4 17.78,60.29 17.78,62.95 19.55,62.95 IC3.2
N$10
  Bottom 0.254: IC4.5 8.88,55.84 9.77,56.73 16.89,56.73 18.66,58.51 18.66,60.29 19.55,60.29 IC3.3
N$11  (via drill 0.61)
  Top 0.254: v5.33,47.84 5.33,51.4 7.11,53.18 IC4.6
  Bottom 0.254: v5.33,47.84 6.22,46.95 22.22,46.95 22.22,57.62 20.44,57.62 IC3.4
N$12
  Bottom 0.254: IC4.10 16,55.84 19.55,55.84 IC3.5
N$13  (via drill 0.61)
  Top 0.254: v12.44,49.62 12.44,56.73 14.22,58.51 IC4.11
  Bottom 0.254: v12.44,49.62 16.89,49.62 16.89,50.51 19.55,53.18 IC3.6
N$14  (via drill 0.61)
  Top 0.254: v84.45,6.95 84.45,14.95 80.89,18.5 IC5.14 | v94.23,6.06 94.23,4.28 JP9.2
  Bottom 0.254: v84.45,6.95 85.34,6.06 v94.23,6.06
N$15
  Top 0.254: IC5.13 83.56,20.28 84.45,21.17 96.01,21.17 96.01,5.17 96.9,4.28 JP9.3
N$16  (via drill 0.61)
  Top 0.254: v27.55,15.84 27.55,6.95 26.67,6.06 26.67,5.17 28.44,3.39 JP11.1
  Bottom 0.254: v27.55,15.84 36.44,15.84 38.22,17.62 U$1.11
N$17  (via drill 0.61)
  Top 0.254: v40.89,2.5 40.89,17.62 U$1.12
  Bottom 0.254: v40.89,2.5 40,1.61 32,1.61 31.11,2.5 JP11.3
N$18
  Top 0.254: U$1.13 42.67,17.62 41.78,16.73 41.78,1.61 33.78,1.61 33.78,2.5 JP11.5
N$19  (via drill 0.61)
  Top 0.254: v41.78,20.28 41.78,23.84 40.89,24.73 U$1.17 | v42.67,15.84 43.56,14.95 43.56,7.84 44.45,6.95 44.45,4.28 JP10.1
  Bottom 0.254: v41.78,20.28 41.78,15.84 v42.67,15.84
N$20
  Top 0.254: R51.2 8.88,14.95 12.44,18.5 U$1.1
  Bottom 0.254: JP10.5 48,2.5 47.11,1.61 41.78,1.61 41.78,4.28 24.89,4.28 22.22,6.95 20.44,6.95 12.44,14.95 8.88,14.95 R51.2
N$21  (via drill 0.61)
  Top 0.254: v40.89,22.06 38.22,24.73 U$1.18 | v52.45,17.62 53.34,16.73 53.34,7.84 55.11,6.06 55.11,5.17 53.34,3.39 JP10.9
  Bottom 0.254: v40.89,22.06 41.78,21.17 48,21.17 51.56,17.62 v52.45,17.62
N$22  (via drill 0.61)
  Top 0.254: v38.22,29.17 35.55,26.51 U$1.19 | v52.45,29.17 56,25.62 56,3.39 54.22,1.61 50.67,1.61 50.67,2.5 JP10.7
  Bottom 0.254: v52.45,29.17 v38.22,29.17
N$23
  Top 0.254: LED1.A 10.66,12.28 12.44,12.28 R39.1
N$24
  Top 0.254: LED2.A 10.66,7.84 12.44,7.84 R40.1
N$25
  Top 0.254: LED3.A 10.66,3.39 12.44,3.39 R45.1
N$26
  Top 0.254: R1.2 T5.B
N$27
  Bottom 0.254: T9.C 30.22,70.95 32.89,73.62 R31.1
N$28  (via drill 0.61)
  Top 0.254: v16,14.95 16,17.62 U$1.2
  Bottom 0.254: v16,14.95 19.55,11.39 48.89,11.39 R4.2
N$29  (via drill 0.61)
  Top 0.254: v128.01,13.17 128.01,18.5 130.68,21.17 JP6.6 | v22.22,10.5 16.89,15.84 16.89,47.84 19.55,50.51 IC3.7
  Bottom 0.254: IC3.7 19.55,50.51 17.78,48.73 6.22,48.73 5.33,49.62 5.33,59.4 12.44,59.4 13.33,60.29 14.22,60.29 IC4.12 | v128.01,13.17 122.68,7.84 98.67,7.84 97.79,6.95 86.23,6.95 83.56,9.61 48.89,9.61 48,10.5 v22.22,10.5
N$30
  Bottom 0.254: U$1.3 17.78,18.5 19.55,20.28 26.67,20.28 26.67,14.95 48,14.95 49.78,16.73 86.23,16.73 88.01,18.5 IC5.11
N$31
  Top 0.254: C1.1 86.23,5.17 86.23,11.39 IC5.5
N$32
  Top 0.254: C1.2 83.56,5.17 83.56,11.39 IC5.4
N$33
  Top 0.254: R5.1 24.89,35.4 24.89,39.84 T5.C
N$34
  Top 0.254: R5.2 34.67,35.4 33.78,36.28 33.78,39.84 T1.B
  Bottom 0.254: R43.1 40.89,32.73 38.22,35.4 R5.2
N$35
  Top 0.254: C2.2 76.45,5.17 75.56,6.06 IC5.1
N$36  (via drill 0.61)
  Top 0.254: v33.78,22.06 33.78,18.5 U$1.9
  Bottom 0.254: v33.78,22.06 35.55,23.84 66.67,23.84 69.34,21.17 QG1.8
N$37
  Top 0.254: R48.2 54.22,35.4 54.22,38.95 T3.B
N$38
  Top 0.254: R3.1 56.89,34.51 56.89,38.95 T3.C
N$39
  Bottom 0.254: R6.1 70.23,32.73 68.45,34.51 66.67,34.51 R3.2 66.67,35.4 65.78,35.4 65.78,38.06 T2.B
N$40
  Top 0.254: C2.1 80.01,5.17 80.01,11.39 IC5.3
N$41
  Top 0.254: C4.1 73.78,4.28 75.56,2.5 78.23,2.5 78.23,11.39 IC5.2
N$42
  Top 0.254: R49.2 83.56,35.4 83.56,38.06 T6.B
N$43
  Top 0.254: R8.1 86.23,35.4 86.23,38.06 T6.C
N$44
  Top 0.254: R41.1 100.45,30.95 96.9,34.51 R8.2
  Bottom 0.254: T4.B 95.12,38.06 95.12,34.51 96.01,34.51 R8.2
N$45
  Top 0.254: R50.2 112.9,34.51 112.9,38.06 T8.B
N$46
  Bottom 0.254: R55.2 4.44,65.62 8,69.18 12.44,69.18 13.33,70.07 T9.B
N$47
  Top 0.254: IC1.16 29.33,91.4 44.45,91.4 R24.1
N$48
  Top 0.254: IC1.7 20.44,76.29 16.89,76.29 16.89,77.18 13.33,77.18 13.33,85.18 14.22,86.07 IC2.12
N$49
  Bottom 0.254: R4.1 52.45,18.5 73.78,18.5 74.67,17.62 84.45,17.62 85.34,18.5 IC5.12
N$50
  Top 0.254: IC4.2 8,63.84 8,65.62 IC4.1 7.11,66.51 7.11,71.84 3.55,75.4 R55.1 4.44,76.29 4.44,77.18 9.77,77.18 11.55,78.96 11.55,86.07 14.22,88.73 IC2.13
N$51
  Top 0.254: IC3.15 28.44,62.95 32,62.95 32,68.29 R33.1
N$52
  Bottom 0.254: IC3.14 28.44,61.18 37.33,61.18 39.11,62.95 44.45,62.95 R34.1
N$53
  Top 0.254: IC3.13 28.44,58.51 31.11,58.51 R35.1
N$54
  Bottom 0.254: IC3.12 28.44,55.84 44.45,55.84 R36.1
N$55
  Top 0.254: IC3.11 R37.1
N$56
  Bottom 0.254: IC3.10 28.44,50.51 44.45,50.51 R38.1
N$57
  Top 0.254: IC1.15 R25.1
N$59
  Top 0.254: R44.1 T8.C
N$60
  Bottom 0.254: R46.1 129.79,30.95 126.23,34.51 R44.2 125.34,34.51 121.79,34.51 121.79,38.06 T7.B
N$61  (via drill 0.61)
  Top 0.254: v89.78,14.95 88.01,13.17 IC5.6
  Bottom 0.254: v89.78,14.95 92.45,17.62 C3.1
N$63
  Top 0.254: IC1.14 29.33,86.07 44.45,86.07 R26.1
N$64
  Top 0.254: IC1.13 29.33,83.4 32,83.4 R27.1
N$65
  Top 0.254: IC1.12 29.33,80.73 45.33,80.73 R28.1
N$66
  Top 0.254: IC1.11 29.33,78.96 32,78.96 R29.1
N$67
  Top 0.254: IC1.10 29.33,76.29 44.45,76.29 R30.1
N$68  (via drill 0.61)
  Top 0.254: v45.33,13.17 45.33,17.62 U$1.14 | v37.33,13.17 37.33,4.28 36.44,3.39 JP11.7
  Bottom 0.254: v45.33,13.17 v37.33,13.17 23.11,13.17 R39.2
N$69  (via drill 0.61)
  Top 0.254: v39.11,9.61 40,8.73 40,4.28 JP11.9 | v47.11,9.61 47.11,20.28 46.22,21.17 46.22,24.73 U$1.15
  Bottom 0.254: R40.2 23.11,8.73 24,9.61 v39.11,9.61 v47.11,9.61
N$70  (via drill 0.61)
  Top 0.254: v26.67,7.84 23.11,4.28 R45.2 | v38.22,8.73 38.22,6.06 JP11.10 | v44.45,8.73 44.45,23.84 43.56,24.73 U$1.16
  Bottom 0.254: v26.67,7.84 27.55,8.73 v38.22,8.73 v44.45,8.73
VCC  (via drill 0.61)
  Top 0.254: C6.1 106.68,17.62 106.68,22.06 | 106.68,22.06 106.68,22.95 107.56,23.84 IC6.OUT 109.34,23.84 109.34,41.62 v112.9,45.17 | IC2.9 16,78.96 16.89,79.84 16.89,90.51 16,91.4 IC2.14 | 16.89,59.4 16.89,64.73 16,65.62 IC4.14 | 16.89,59.4 16.89,54.06 16,53.18 IC4.9 | C7.1 64.89,4.28 71.12,4.28 C4.2 71.12,5.17 72,6.06 72,14.95 74.67,17.62 | 74.67,17.62 75.56,18.5 IC5.16 | R51.1 8.88,30.06 C8.1 8,30.95 10.66,33.62 10.66,59.4 16.89,59.4 | 28.44,13.17 28.44,6.06 | 28.44,13.17 28.44,17.62 U$1.7 | 28.44,13.17 32,16.73 32,23.84 32.89,24.73 U$1.20 | 28.44,6.06 31.11,6.06 JP11.4 | 28.44,6.06 JP11.2 | 106.68,22.06 79.12,22.06 79.12,17.62 74.67,17.62
  Bottom 0.254: C9.1 115.56,23.84 109.34,23.84 IC6.OUT | v112.9,45.17 128.01,45.17 JP8.1 | 4.44,64.73 4.44,46.06 JP7.1 | 4.44,64.73 12.44,64.73 13.33,65.62 14.22,65.62 IC4.14 | 4.44,64.73 2.66,64.73 2.66,77.18 5.33,79.84 9.77,79.84 10.66,78.96 14.22,78.96 IC2.9 | QG1.14 55.11,21.17 56.89,19.39 75.56,19.39 IC5.16 | C7.1 64.89,4.28 44.45,4.28 JP10.2 41.78,6.95 32,6.95 31.11,6.06 JP11.4 | R51.1 8.88,24.73 9.77,23.84 32,23.84 32.89,24.73 U$1.20
VDD
  Top 0.254: JP12.4 126.23,4.28 126.23,6.95 R52.2 125.34,6.95 123.57,8.73 123.57,27.39 R46.2
  Bottom 0.254: JP7.2 4.44,43.4 3.55,43.4 2.66,42.51 2.66,32.73 25.78,32.73 31.11,38.06 T1.E 31.11,43.4 40.89,43.4 R43.2 41.78,43.4 46.22,47.84 61.34,47.84 66.67,42.51 | 66.67,42.51 70.23,42.51 R6.2 71.12,42.51 75.56,46.95 90.67,46.95 95.12,42.51 | 66.67,42.51 63.11,42.51 63.11,39.84 T2.E | 95.12,42.51 99.56,42.51 100.45,41.62 | 95.12,42.51 92.45,42.51 92.45,39.84 T4.E | R46.2 119.12,30.95 119.12,38.06 T7.E 119.12,39.84 119.12,40.73 120.9,42.51 | 120.9,42.51 121.79,43.4 128.01,43.4 JP8.2 | 100.45,41.62 101.34,42.51 120.9,42.51 | 100.45,41.62 R41.2
VEE
  Top 0.254: R7.1 69.34,47.84 65.78,47.84 R2.1 64.89,47.84 47.11,47.84 47.11,56.73 44.45,59.4 | IC3.9 26.67,47.84 24.89,49.62 24.89,70.95 27.55,73.62 IC1.9 29.33,73.62 29.33,70.95 33.78,70.95 34.67,70.07 34.67,69.18 44.45,59.4 | 118.23,70.95 118.23,66.51 R54.1 118.23,65.62 | 118.23,86.07 118.23,81.62 R13.1 118.23,80.73 118.23,76.29 R15.1 118.23,75.4 118.23,70.95 | 118.23,91.4 118.23,86.07 | 118.23,86.07 R11.1 | 118.23,70.95 R17.1 | R42.1 94.23,48.73 96.9,48.73 R47.1 | 118.23,55.84 118.23,50.51 R23.1 | 118.23,65.62 118.23,55.84 | 118.23,55.84 R21.1 | 130.68,73.62 130.68,78.07 R14.1 130.68,78.96 130.68,83.4 R12.1 130.68,84.29 130.68,88.73 R10.1 | 130.68,65.62 130.68,68.29 | 130.68,65.62 130.68,63.84 R19.1 130.68,62.95 130.68,58.51 R20.1 130.68,57.62 130.68,53.18 | 132.46,40.73 129.79,40.73 JP8.3 | 132.46,40.73 132.46,51.4 130.68,53.18 | 130.68,53.18 R22.1 | 132.46,40.73 132.46,37.17 126.23,30.95 126.23,16.73 R52.1 | 130.68,68.29 130.68,73.62 | 130.68,73.62 R16.1 | 130.68,68.29 R18.1 | 118.23,65.62 130.68,65.62 | 44.45,59.4 52.45,67.4 52.45,92.29 54.22,94.07 118.23,94.07 118.23,91.4 | 118.23,91.4 R9.1
  Bottom 0.254: IC3.9 26.67,47.84 22.22,43.4 11.55,43.4 8.88,40.73 7.11,40.73 JP7.3 | R47.1 97.79,47.84 115.56,47.84 118.23,50.51 R23.1 | R53.2 120.9,16.73 125.34,16.73 R52.1

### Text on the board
Dimension: B-7971 Nixie Controller | Revision 1 | Jon M. Dugan <jdugan@x1024.net>
tNames: Data In | Data Out | ICSP | RS-232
